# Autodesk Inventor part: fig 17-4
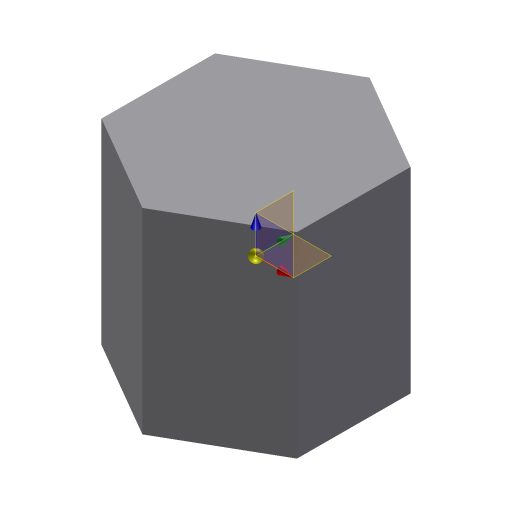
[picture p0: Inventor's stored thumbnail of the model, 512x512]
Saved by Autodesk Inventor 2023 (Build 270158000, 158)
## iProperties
Created: 2008-06
Part Number: fig 17-4
Document SubType Name: Modeling
Designer: CADCIM
Mass: 866.025 g
Surface Area: 519.615 cm^2
Volume: 866.025 cm^3
Density: 1 g/cm^3
Material: Generic
Appearance: Default
Author: CADCIM
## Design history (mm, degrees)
sketch "Sketch1"
  geometry: L1 (0.184, 57.735)-(50.092, 28.708); L2 (50.092, 28.708)-(49.908, -29.027); L3 (49.908, -29.027)-(-0.184, -57.735); L4 (-0.184, -57.735)-(-50.092, -28.708); L5 (-50.092, -28.708)-(-49.908, 29.027); L6 (-49.908, 29.027)-(0.184, 57.735); 1 further point
  constraints: 12 end point, 13 other
  dimensions: "d0" = 100 distance between parallel lines of L2 L5
extrude "Extrusion1" new body sketch "Sketch1" distance "d1" = 100; taper "d2" = 0 deg
body "Solid1"
